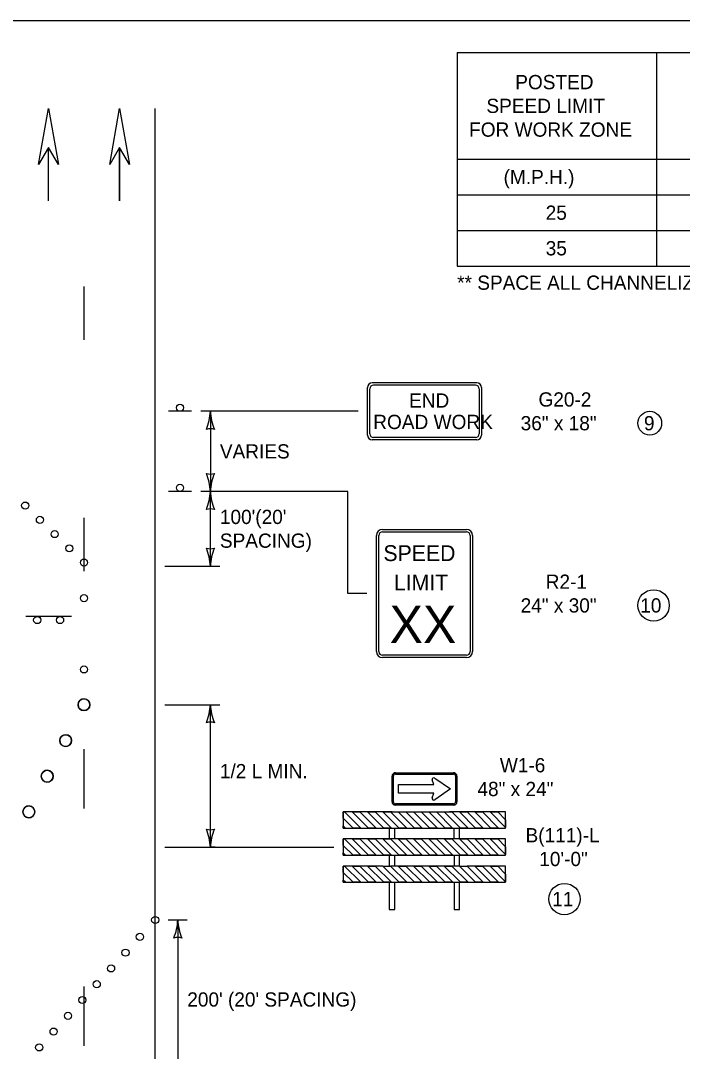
# Model space of a CAD drawing. Extents: x 49991.4 to 50021, y 49987.6 to 50011.4.
# Drawn here: x 50001.9 to 50004.689, y 49994.657 to 49998.999 of the extents above; entities that cross this region are included whole.
import ezdxf

# ---------------------------------------------------------------- set-up
doc = ezdxf.new("R2010")
doc.units = 0
for name, color, linetype in [('Level 1', 7, 'Continuous'), ('Level 2', 7, 'Continuous'), ('Level 3', 7, 'Continuous')]:
    doc.layers.add(name, color=color, linetype=linetype)

# ---------------------------------------------------------------- blocks, each defined once
blk = doc.blocks.new('ARR')
at = {"layer": 'Level 3'}
for centre, radius, start, end in [((1.53, 37.02), 37.05, 247.45601, 267.63952), ((-21.37, 0), 9.13, 342.13882, 17.86118), ((1.92, -38.79), 38.83, 92.82731, 112.07716)]:
    blk.add_arc(centre, radius, start, end, dxfattribs=at)
blk = doc.blocks.new('G20-2')
at = {"layer": 'Level 1'}
for p, q in [((-0.2403, -0.1004), (-0.2403, 0.0996)), ((-0.2303, -0.0954), (-0.2303, 0.0946)), ((0.2197, 0.1196), (-0.2203, 0.1196)), ((0.2147, 0.1096), (-0.2153, 0.1096)), ((0.2297, 0.0946), (0.2297, -0.0954)), ((0.2397, 0.0996), (0.2397, -0.1004)), ((0.2196, -0.1204), (-0.2204, -0.1204)), ((0.2147, -0.1104), (-0.2153, -0.1104))]:
    blk.add_line(p, q, dxfattribs=at)
for centre, radius, start, end in [((-0.2203, 0.0996), 0.02, 90, 180), ((-0.2153, 0.0946), 0.015, 90, 180), ((0.2147, 0.0946), 0.015, 360, 90), ((0.2197, 0.0996), 0.02, 360, 90), ((-0.2204, -0.1004), 0.02, 180, 270), ((-0.2153, -0.0954), 0.015, 180, 270), ((0.2147, -0.0954), 0.015, 270, 360), ((0.2196, -0.1004), 0.02, 270, 360)]:
    blk.add_arc(centre, radius, start, end, dxfattribs=at)
for s, p in [('END', (-0.0655, 0.015)), ('ROAD WORK', (-0.2162, -0.075))]:
    blk.add_text(s, height=0.06, rotation=360, dxfattribs=at).set_placement(p)

msp = doc.modelspace()

# ---------------------------------------------------------------- linework, layer by layer
at = {"layer": 'Level 1'}
for p, q in [((50002.4673, 49996.0633), (50002.4673, 49998.6295)), ((50002.0174, 49998.2394), (50002.0174, 49998.4653)), ((50002.0178, 49998.2394), (50002.0178, 49998.4653)), ((50002.3174, 49998.2394), (50002.3174, 49998.4653)), ((50002.3178, 49998.2394), (50002.3178, 49998.4653)), ((50002.1674, 49997.6544), (50002.1674, 49997.8784)), ((50002.6197, 49997.3532), (50002.5237, 49997.3532)), ((50002.6197, 49997.0157), (50002.5237, 49997.0157)), ((50002.1674, 49996.6804), (50002.1674, 49996.9044)), ((50003.3994, 49996.3408), (50003.3994, 49996.8302)), ((50003.4099, 49996.3408), (50003.4099, 49996.8302)), ((50003.4247, 49996.8556), (50003.7791, 49996.8556)), ((50003.4247, 49996.845), (50003.7791, 49996.845)), ((50003.6019, 49996.8556), (50003.6019, 49996.8556)), ((50003.7939, 49996.8302), (50003.7939, 49996.3408)), ((50003.8044, 49996.8302), (50003.8044, 49996.3408)), ((50002.0183, 49996.4891), (50001.9223, 49996.4891)), ((50002.1143, 49996.4891), (50002.0183, 49996.4891)), ((50003.7791, 49996.326), (50003.4247, 49996.326)), ((50003.7791, 49996.3155), (50003.4247, 49996.3155)), ((50002.4673, 49993.9404), (50002.4673, 49996.0633)), ((50002.1674, 49995.6804), (50002.1674, 49995.9304)), ((50003.4794, 49995.8307), (50003.7244, 49995.8307)), ((50003.4794, 49995.825), (50003.7244, 49995.825)), ((50003.4651, 49995.7082), (50003.4651, 49995.8165)), ((50003.4708, 49995.7082), (50003.4708, 49995.8165)), ((50003.4924, 49995.7441), (50003.4924, 49995.7806)), ((50003.4924, 49995.7806), (50003.6408, 49995.7806)), ((50003.6408, 49995.7806), (50003.6344, 49995.8002)), ((50003.6449, 49995.808), (50003.7114, 49995.7623)), ((50003.733, 49995.8165), (50003.733, 49995.7082)), ((50003.7387, 49995.8165), (50003.7387, 49995.7082)), ((50003.6306, 49995.7441), (50003.4924, 49995.7441)), ((50003.6408, 49995.7441), (50003.6306, 49995.7441)), ((50003.6344, 49995.7245), (50003.6408, 49995.7441)), ((50003.7114, 49995.7623), (50003.6449, 49995.7166)), ((50003.7244, 49995.6996), (50003.4794, 49995.6996)), ((50003.7244, 49995.6939), (50003.4794, 49995.6939)), ((50003.3339, 49995.597), (50003.2655, 49995.6654)), ((50003.2655, 49995.6654), (50003.3339, 49995.597)), ((50003.3662, 49995.597), (50003.2978, 49995.6654)), ((50003.3662, 49995.597), (50003.2978, 49995.6654)), ((50003.3984, 49995.597), (50003.33, 49995.6654)), ((50003.33, 49995.6654), (50003.3984, 49995.597)), ((50003.4306, 49995.597), (50003.3622, 49995.6654)), ((50003.4306, 49995.597), (50003.3622, 49995.6654)), ((50003.4629, 49995.597), (50003.3945, 49995.6654)), ((50003.3945, 49995.6654), (50003.4629, 49995.597)), ((50003.4952, 49995.597), (50003.4268, 49995.6654)), ((50003.5274, 49995.597), (50003.459, 49995.6654)), ((50003.459, 49995.6654), (50003.4989, 49995.6654)), ((50003.4794, 49995.6654), (50003.7244, 49995.6654)), ((50003.5596, 49995.597), (50003.4912, 49995.6654)), ((50003.5918, 49995.597), (50003.5234, 49995.6654)), ((50003.624, 49995.597), (50003.5556, 49995.6654)), ((50003.6562, 49995.597), (50003.5878, 49995.6654)), ((50003.6884, 49995.597), (50003.62, 49995.6654)), ((50003.7206, 49995.597), (50003.6522, 49995.6654)), ((50003.753, 49995.597), (50003.6846, 49995.6654)), ((50003.7387, 49995.6654), (50003.7074, 49995.6654)), ((50003.7853, 49995.597), (50003.7169, 49995.6654)), ((50003.8175, 49995.597), (50003.7491, 49995.6654)), ((50003.8175, 49995.597), (50003.7491, 49995.6654)), ((50003.8497, 49995.597), (50003.7813, 49995.6654)), ((50003.7813, 49995.6654), (50003.8497, 49995.597)), ((50003.882, 49995.597), (50003.8136, 49995.6654)), ((50003.882, 49995.597), (50003.8136, 49995.6654)), ((50003.9142, 49995.597), (50003.8458, 49995.6654)), ((50003.8458, 49995.6654), (50003.9142, 49995.597)), ((50003.9439, 49995.5996), (50003.878, 49995.6654)), ((50003.9439, 49995.5996), (50003.878, 49995.6654)), ((50003.9439, 49995.6319), (50003.9103, 49995.6654)), ((50003.9103, 49995.6654), (50003.9439, 49995.6319)), ((50003.3017, 49995.597), (50003.2599, 49995.6388)), ((50003.3017, 49995.597), (50003.2599, 49995.6388)), ((50003.2695, 49995.597), (50003.2599, 49995.6065)), ((50003.2599, 49995.6065), (50003.2695, 49995.597)), ((50003.4765, 49995.5515), (50003.4765, 49995.597)), ((50003.7273, 49995.5515), (50003.7273, 49995.597)), ((50003.3017, 49995.4831), (50003.2599, 49995.5248)), ((50003.3017, 49995.4831), (50003.2599, 49995.5248)), ((50003.3339, 49995.4831), (50003.2655, 49995.5515)), ((50003.2655, 49995.5515), (50003.3339, 49995.4831)), ((50003.3662, 49995.4831), (50003.2978, 49995.5515)), ((50003.3662, 49995.4831), (50003.2978, 49995.5515)), ((50003.3984, 49995.4831), (50003.33, 49995.5515)), ((50003.33, 49995.5515), (50003.3984, 49995.4831)), ((50003.4306, 49995.4831), (50003.3622, 49995.5515)), ((50003.4306, 49995.4831), (50003.3622, 49995.5515)), ((50003.4629, 49995.4831), (50003.3945, 49995.5515)), ((50003.3945, 49995.5515), (50003.4629, 49995.4831)), ((50003.4651, 49995.5131), (50003.4268, 49995.5515)), ((50003.4651, 49995.5453), (50003.459, 49995.5515)), ((50003.5274, 49995.4831), (50003.4651, 49995.5453)), ((50003.5596, 49995.4831), (50003.4912, 49995.5515)), ((50003.5918, 49995.4831), (50003.5234, 49995.5515)), ((50003.6241, 49995.4831), (50003.5557, 49995.5515)), ((50003.6563, 49995.4831), (50003.5879, 49995.5515)), ((50003.6885, 49995.4831), (50003.6201, 49995.5515)), ((50003.7208, 49995.4831), (50003.6524, 49995.5515)), ((50003.753, 49995.4831), (50003.6846, 49995.5515)), ((50003.7853, 49995.4831), (50003.7169, 49995.5515)), ((50003.8175, 49995.4831), (50003.7491, 49995.5515)), ((50003.8175, 49995.4831), (50003.7491, 49995.5515)), ((50003.8497, 49995.4831), (50003.7813, 49995.5515)), ((50003.7813, 49995.5515), (50003.8497, 49995.4831)), ((50003.882, 49995.4831), (50003.8136, 49995.5515)), ((50003.882, 49995.4831), (50003.8136, 49995.5515)), ((50003.9142, 49995.4831), (50003.8458, 49995.5515)), ((50003.8458, 49995.5515), (50003.9142, 49995.4831)), ((50003.9439, 49995.4857), (50003.878, 49995.5515)), ((50003.9439, 49995.4857), (50003.878, 49995.5515)), ((50003.9439, 49995.5179), (50003.9103, 49995.5515)), ((50003.9103, 49995.5515), (50003.9439, 49995.5179)), ((50003.2695, 49995.4831), (50003.2599, 49995.4926)), ((50003.2599, 49995.4926), (50003.2695, 49995.4831)), ((50003.4952, 49995.4831), (50003.4651, 49995.5131)), ((50003.3339, 49995.3692), (50003.2655, 49995.4376)), ((50003.2655, 49995.4376), (50003.3339, 49995.3692)), ((50003.3662, 49995.3692), (50003.2978, 49995.4376)), ((50003.3662, 49995.3692), (50003.2978, 49995.4376)), ((50003.3984, 49995.3692), (50003.33, 49995.4376)), ((50003.33, 49995.4376), (50003.3984, 49995.3692)), ((50003.4306, 49995.3692), (50003.3622, 49995.4376)), ((50003.4306, 49995.3692), (50003.3622, 49995.4376)), ((50003.4629, 49995.3692), (50003.3945, 49995.4376)), ((50003.3945, 49995.4376), (50003.4629, 49995.3692)), ((50003.4952, 49995.3692), (50003.4268, 49995.4376)), ((50003.4952, 49995.3692), (50003.4268, 49995.4376)), ((50003.5274, 49995.3692), (50003.459, 49995.4376)), ((50003.459, 49995.4376), (50003.5274, 49995.3692)), ((50003.5596, 49995.3692), (50003.4912, 49995.4376)), ((50003.5596, 49995.3692), (50003.4912, 49995.4376)), ((50003.5918, 49995.3692), (50003.5234, 49995.4376)), ((50003.5234, 49995.4376), (50003.5918, 49995.3692)), ((50003.6241, 49995.3692), (50003.5557, 49995.4376)), ((50003.6241, 49995.3692), (50003.5557, 49995.4376)), ((50003.6563, 49995.3692), (50003.5879, 49995.4376)), ((50003.5879, 49995.4376), (50003.6563, 49995.3692)), ((50003.6885, 49995.3692), (50003.6201, 49995.4376)), ((50003.6885, 49995.3692), (50003.6201, 49995.4376)), ((50003.7208, 49995.3692), (50003.6524, 49995.4376)), ((50003.6524, 49995.4376), (50003.7208, 49995.3692)), ((50003.753, 49995.3692), (50003.6846, 49995.4376)), ((50003.753, 49995.3692), (50003.6846, 49995.4376)), ((50003.7853, 49995.3692), (50003.7169, 49995.4376)), ((50003.7169, 49995.4376), (50003.7853, 49995.3692)), ((50003.8175, 49995.3692), (50003.7491, 49995.4376)), ((50003.8175, 49995.3692), (50003.7491, 49995.4376)), ((50003.8497, 49995.3692), (50003.7813, 49995.4376)), ((50003.7813, 49995.4376), (50003.8497, 49995.3692)), ((50003.882, 49995.3692), (50003.8136, 49995.4376)), ((50003.882, 49995.3692), (50003.8136, 49995.4376)), ((50003.9142, 49995.3692), (50003.8458, 49995.4376)), ((50003.8458, 49995.4376), (50003.9142, 49995.3692)), ((50003.9439, 49995.3717), (50003.878, 49995.4376)), ((50003.9439, 49995.3717), (50003.878, 49995.4376)), ((50003.9439, 49995.4039), (50003.9103, 49995.4376)), ((50003.9103, 49995.4376), (50003.9439, 49995.4039)), ((50003.3017, 49995.3692), (50003.2599, 49995.4109)), ((50003.3017, 49995.3692), (50003.2599, 49995.4109)), ((50003.2695, 49995.3692), (50003.2599, 49995.3787)), ((50003.2599, 49995.3787), (50003.2695, 49995.3692)), ((50002.1674, 49994.6804), (50002.1674, 49994.9304))]:
    msp.add_line(p, q, dxfattribs=at)
for points in [[(49999.3835, 49998.9992), (50016.7501, 49998.9992), (50016.7501, 49987.7988), (49999.3835, 49987.7988)], [(50001.9758, 49998.393), (50002.0174, 49998.6295), (50002.0594, 49998.393), (50002.0174, 49998.4652)], [(50002.2758, 49998.393), (50002.3174, 49998.6295), (50002.3594, 49998.393), (50002.3174, 49998.4652)]]:
    msp.add_lwpolyline(points, close=True, dxfattribs=at)
for points in [[(50003.4651, 49995.6654), (50003.2599, 49995.6654), (50003.2599, 49995.597), (50003.4651, 49995.597)], [(50003.2599, 49995.6388), (50003.2599, 49995.6654), (50003.2655, 49995.6654)], [(50003.2978, 49995.6654), (50003.33, 49995.6654)], [(50003.3622, 49995.6654), (50003.3945, 49995.6654)], [(50003.5274, 49995.597), (50003.4952, 49995.597), (50003.4268, 49995.6654), (50003.459, 49995.6654), (50003.5274, 49995.597)], [(50003.4651, 49995.597), (50003.9439, 49995.597), (50003.9439, 49995.6654), (50003.7387, 49995.6654)], [(50003.4912, 49995.6654), (50003.4989, 49995.6654), (50003.5234, 49995.6654), (50003.5918, 49995.597), (50003.5596, 49995.597), (50003.4912, 49995.6654)], [(50003.5556, 49995.6654), (50003.5878, 49995.6654), (50003.6562, 49995.597), (50003.624, 49995.597), (50003.5556, 49995.6654)], [(50003.62, 49995.6654), (50003.6522, 49995.6654), (50003.7206, 49995.597), (50003.6884, 49995.597), (50003.62, 49995.6654)], [(50003.6846, 49995.6654), (50003.7074, 49995.6654), (50003.7169, 49995.6654), (50003.7853, 49995.597), (50003.753, 49995.597), (50003.6846, 49995.6654)], [(50003.7491, 49995.6654), (50003.7813, 49995.6654)], [(50003.8136, 49995.6654), (50003.8458, 49995.6654)], [(50003.878, 49995.6654), (50003.9103, 49995.6654)], [(50003.2695, 49995.597), (50003.2599, 49995.597), (50003.2599, 49995.6065)], [(50003.9439, 49995.6319), (50003.9439, 49995.5996)], [(50003.3339, 49995.597), (50003.3017, 49995.597)], [(50003.3984, 49995.597), (50003.3662, 49995.597)], [(50003.4629, 49995.597), (50003.4306, 49995.597)], [(50003.4537, 49995.597), (50003.4537, 49995.5515)], [(50003.7501, 49995.5514), (50003.7501, 49995.597)], [(50003.8497, 49995.597), (50003.8175, 49995.597)], [(50003.9142, 49995.597), (50003.882, 49995.597)], [(50003.4651, 49995.5515), (50003.2599, 49995.5515), (50003.2599, 49995.4831), (50003.9439, 49995.4831), (50003.9439, 49995.5515), (50003.4651, 49995.5515)], [(50003.2599, 49995.5248), (50003.2599, 49995.5515), (50003.2655, 49995.5515)], [(50003.2978, 49995.5515), (50003.33, 49995.5515)], [(50003.3622, 49995.5515), (50003.3945, 49995.5515)], [(50003.5274, 49995.4831), (50003.4952, 49995.4831), (50003.4651, 49995.5131), (50003.4268, 49995.5515), (50003.4537, 49995.5515), (50003.459, 49995.5515), (50003.4651, 49995.5453), (50003.5274, 49995.4831)], [(50003.4912, 49995.5515), (50003.5234, 49995.5515), (50003.5918, 49995.4831), (50003.5596, 49995.4831), (50003.4912, 49995.5515)], [(50003.5557, 49995.5515), (50003.5879, 49995.5515), (50003.6563, 49995.4831), (50003.6241, 49995.4831), (50003.5557, 49995.5515)], [(50003.6201, 49995.5515), (50003.6524, 49995.5515), (50003.7208, 49995.4831), (50003.6885, 49995.4831), (50003.6201, 49995.5515)], [(50003.6846, 49995.5515), (50003.7169, 49995.5515), (50003.7853, 49995.4831), (50003.753, 49995.4831), (50003.6846, 49995.5515)], [(50003.7491, 49995.5515), (50003.7813, 49995.5515)], [(50003.8136, 49995.5515), (50003.8458, 49995.5515)], [(50003.878, 49995.5515), (50003.9103, 49995.5515)], [(50003.9439, 49995.5179), (50003.9439, 49995.4857)], [(50003.2695, 49995.4831), (50003.2599, 49995.4831), (50003.2599, 49995.4926)], [(50003.3339, 49995.4831), (50003.3017, 49995.4831)], [(50003.3984, 49995.4831), (50003.3662, 49995.4831)], [(50003.4629, 49995.4831), (50003.4306, 49995.4831)], [(50003.4537, 49995.4831), (50003.4537, 49995.4376)], [(50003.4765, 49995.4376), (50003.4765, 49995.4831)], [(50003.7273, 49995.4831), (50003.7273, 49995.4376)], [(50003.7501, 49995.4376), (50003.7501, 49995.4831)], [(50003.8497, 49995.4831), (50003.8175, 49995.4831)], [(50003.9142, 49995.4831), (50003.882, 49995.4831)], [(50003.2599, 49995.4109), (50003.2599, 49995.4376), (50003.2655, 49995.4376)], [(50003.4268, 49995.4376), (50003.2599, 49995.4376), (50003.2599, 49995.3692), (50003.9439, 49995.3692), (50003.9439, 49995.4376), (50003.7813, 49995.4376)], [(50003.2978, 49995.4376), (50003.33, 49995.4376)], [(50003.3622, 49995.4376), (50003.3945, 49995.4376)], [(50003.4268, 49995.4376), (50003.459, 49995.4376)], [(50003.7491, 49995.4376), (50003.459, 49995.4376)], [(50003.4912, 49995.4376), (50003.5234, 49995.4376)], [(50003.5557, 49995.4376), (50003.5879, 49995.4376)], [(50003.6201, 49995.4376), (50003.6524, 49995.4376)], [(50003.6846, 49995.4376), (50003.7169, 49995.4376)], [(50003.7491, 49995.4376), (50003.7813, 49995.4376)], [(50003.8136, 49995.4376), (50003.8458, 49995.4376)], [(50003.878, 49995.4376), (50003.9103, 49995.4376)], [(50003.9439, 49995.4039), (50003.9439, 49995.3717)], [(50003.2695, 49995.3692), (50003.2599, 49995.3692), (50003.2599, 49995.3787)], [(50003.3339, 49995.3692), (50003.3017, 49995.3692)], [(50003.3984, 49995.3692), (50003.3662, 49995.3692)], [(50003.4629, 49995.3692), (50003.4306, 49995.3692)], [(50003.4537, 49995.369), (50003.4537, 49995.2551), (50003.4765, 49995.2551), (50003.4765, 49995.369)], [(50003.5274, 49995.3692), (50003.4952, 49995.3692)], [(50003.5918, 49995.3692), (50003.5596, 49995.3692)], [(50003.6563, 49995.3692), (50003.6241, 49995.3692)], [(50003.7208, 49995.3692), (50003.6885, 49995.3692)], [(50003.7273, 49995.369), (50003.7273, 49995.2551), (50003.7501, 49995.2551), (50003.7501, 49995.369)], [(50003.7853, 49995.3692), (50003.753, 49995.3692)], [(50003.8497, 49995.3692), (50003.8175, 49995.3692)], [(50003.9142, 49995.3692), (50003.882, 49995.3692)]]:
    msp.add_lwpolyline(points, dxfattribs=at)
for centre, radius in [((50002.5717, 49997.3684), 0.0152), ((50002.5717, 49997.0309), 0.0152), ((50001.9194, 49996.956), 0.015), ((50001.9814, 49996.896), 0.015), ((50002.0434, 49996.836), 0.015), ((50002.1054, 49996.776), 0.015), ((50002.1674, 49996.716), 0.015), ((50002.1672, 49996.566), 0.015), ((50001.9703, 49996.4739), 0.0152), ((50002.0663, 49996.4739), 0.0152), ((50002.1672, 49996.266), 0.015), ((50002.1672, 49996.1173), 0.025), ((50002.0897, 49995.966), 0.025), ((50002.0122, 49995.816), 0.025), ((50001.9348, 49995.666), 0.025), ((50002.4673, 49995.2104), 0.015), ((50002.4026, 49995.1394), 0.015), ((50002.342, 49995.0728), 0.015), ((50002.2814, 49995.0063), 0.015), ((50002.2209, 49994.9397), 0.015), ((50002.1603, 49994.8732), 0.015), ((50002.0997, 49994.8066), 0.015), ((50002.0391, 49994.7401), 0.015), ((50001.9785, 49994.6735), 0.015)]:
    msp.add_circle(centre, radius, dxfattribs=at)
for centre, radius, start, end in [((50003.4247, 49996.8302), 0.0253, 90, 180), ((50003.4247, 49996.8302), 0.0148, 90, 180), ((50003.7791, 49996.8302), 0.0253, 0, 90), ((50003.7791, 49996.8302), 0.0148, 0, 90), ((50003.4247, 49996.3408), 0.0253, 180, 270), ((50003.4247, 49996.3408), 0.0148, 180, 270), ((50003.7791, 49996.3408), 0.0148, 270, 360), ((50003.7791, 49996.3408), 0.0253, 270, 360), ((50002.1672, 49996.1173), 0.025, 357.0759, 177.0759), ((50002.1672, 49996.1173), 0.025, 177.0759, 357.0759), ((50002.0897, 49995.966), 0.025, 177.0759, 357.0759), ((50002.0897, 49995.966), 0.025, 357.0759, 177.0759), ((50002.0122, 49995.816), 0.025, 357.0759, 177.0759), ((50003.4794, 49995.8165), 0.0142, 90, 180), ((50003.4794, 49995.8165), 0.00855, 90, 180), ((50003.7244, 49995.8165), 0.0142, 0, 90), ((50003.7244, 49995.8165), 0.00855, 0, 90), ((50002.0122, 49995.816), 0.025, 177.0759, 357.0759), ((50003.641, 49995.8023), 0.00695, 55.4806, 197.9582), ((50001.9348, 49995.666), 0.025, 357.0759, 177.0759), ((50003.4794, 49995.7082), 0.0142, 180, 270), ((50003.4794, 49995.7082), 0.00855, 180, 270), ((50003.641, 49995.7224), 0.00695, 162.0418, 304.5194), ((50003.7244, 49995.7082), 0.0142, 270, 0), ((50003.7244, 49995.7082), 0.00855, 270, 0), ((50001.9348, 49995.666), 0.025, 177.0759, 357.0759)]:
    msp.add_arc(centre, radius, start, end, dxfattribs=at)
at = {"layer": 'Level 2'}
for p, q in [((50003.7395, 49998.8652), (50007.6695, 49998.8652)), ((50003.7395, 49998.8652), (50003.7395, 49997.9652)), ((50004.5795, 49998.8652), (50004.5795, 49997.9652)), ((50003.7395, 49998.4152), (50007.6695, 49998.4152)), ((50003.7395, 49998.2652), (50007.6695, 49998.2652)), ((50003.7395, 49998.1152), (50007.6695, 49998.1152)), ((50003.7395, 49997.9652), (50007.6695, 49997.9652))]:
    msp.add_line(p, q, dxfattribs=at)
for centre, radius in [((50004.5511, 49997.3032), 0.0501), ((50004.5672, 49996.5355), 0.0662), ((50004.1918, 49995.2983), 0.0662)]:
    msp.add_circle(centre, radius, dxfattribs=at)
at = {"layer": 'Level 3'}
for p, q in [((50003.3218, 49997.3532), (50002.6597, 49997.3532)), ((50002.6997, 49997.3532), (50002.6997, 49997.0157)), ((50003.2789, 49997.0157), (50002.6597, 49997.0157)), ((50002.6997, 49996.7011), (50002.6997, 49997.0157)), ((50002.5073, 49996.7011), (50002.7397, 49996.7011)), ((50002.5073, 49996.1173), (50002.7397, 49996.1173)), ((50002.5073, 49995.5173), (50003.2199, 49995.5173)), ((50002.5223, 49995.2104), (50002.6023, 49995.2104)), ((50002.5623, 49995.2104), (50002.5623, 49994.5404))]:
    msp.add_line(p, q, dxfattribs=at)
for points in [[(50003.3594, 49996.5855), (50003.2794, 49996.5855), (50003.2794, 49997.0157)], [(50002.7197, 49995.5173), (50002.6997, 49995.5173), (50002.6997, 49996.1173)]]:
    msp.add_lwpolyline(points, dxfattribs=at)

# ---------------------------------------------------------------- block references
at = {"layer": 'Level 2', "xscale": 0.006, "yscale": 0.006}
for p, rotation in [((50002.6997, 49997.3532), 90), ((50002.6997, 49997.0157), -90), ((50002.6997, 49996.7011), -90), ((50002.6997, 49995.5173), -90)]:
    msp.add_blockref('ARR', p, dxfattribs=dict(at, rotation=rotation))
at = {"layer": 'Level 3', "xscale": 1.001, "yscale": 1.001}
msp.add_blockref('G20-2', (50003.6023, 49997.3536), dxfattribs=at)
at = {"layer": 'Level 3', "xscale": 0.006, "yscale": 0.006, "rotation": 90}
for p in [(50002.6997, 49997.0157), (50002.6997, 49996.1173), (50002.5623, 49995.2104)]:
    msp.add_blockref('ARR', p, dxfattribs=at)

# ---------------------------------------------------------------- texts
at = {"layer": 'Level 1'}
for s, height, p in [('SPEED', 0.06695, (50003.4288, 49996.7223)), ('LIMIT', 0.06695, (50003.4731, 49996.5985)), ('XX', 0.15772, (50003.4548, 49996.3766))]:
    msp.add_text(s, height=height, dxfattribs=at).set_placement(p)
at = {"layer": 'Level 2'}
for s, height, p in [('POSTED', 0.06, (50003.9842, 49998.7102)), ('SPEED LIMIT', 0.06, (50003.8629, 49998.6102)), ('FOR WORK ZONE', 0.06, (50003.7899, 49998.5102)), ('(M.P.H.)', 0.06, (50003.9351, 49998.3102)), ('25', 0.06, (50004.1125, 49998.1602)), ('35', 0.06, (50004.1126, 49998.0102)), ('** SPACE ALL CHANNELIZING DEVICES AT "G" UNLESS OTHERWISE NOTED.', 0.06, (50003.7395, 49997.8652)), ('G20-2', 0.06, (50004.0822, 49997.3732)), ('36" x 18"', 0.06, (50004.007, 49997.2732)), ('9', 0.06, (50004.5266, 49997.2732)), ('VARIES', 0.06, (50002.7397, 49997.1545)), ("100'(20'", 0.06, (50002.7397, 49996.8784)), ('SPACING)', 0.06, (50002.7397, 49996.7784)), ('R2-1', 0.06, (50004.1126, 49996.6055)), ('24" x 30"', 0.06, (50004.007, 49996.5055)), ('10', 0.06006, (50004.5108, 49996.5055)), ('1/2 L MIN.', 0.06, (50002.7397, 49995.8073)), ('W1-6', 0.06, (50003.9194, 49995.8323)), ('48" x 24"', 0.06, (50003.825, 49995.7323)), ('B(111)-L', 0.06, (50004.0276, 49995.5373)), ('10\'-0"', 0.06, (50004.0855, 49995.4373)), ('11', 0.06006, (50004.1397, 49995.2684)), ("200' (20' SPACING)", 0.06, (50002.6023, 49994.8454))]:
    msp.add_text(s, height=height, dxfattribs=at).set_placement(p)

doc.saveas('drawing.dxf')
